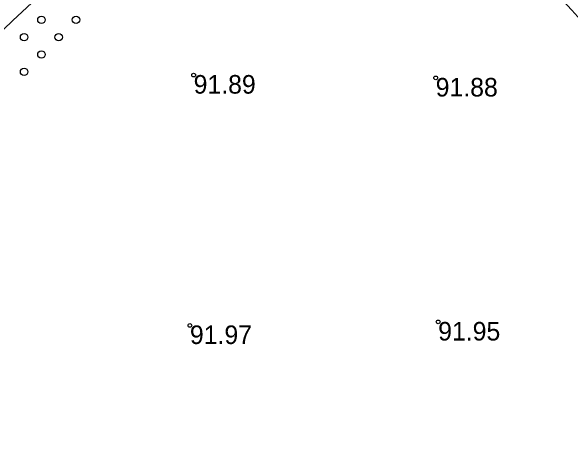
# Model space of a CAD drawing. Extents: x 316000 to 728450, y 314368 to 726000.
# Drawn here: x 726103.9 to 726217, y 315036.8 to 315127.7 of the extents above; entities that cross this region are included whole.
import ezdxf

# ---------------------------------------------------------------- set-up
doc = ezdxf.new("R2010")
doc.units = 0
for name, color, linetype in [('RELJ_AATZ_####_TKST_#', 7, 'Continuous'), ('RELJ_ELEM_####_####_#', 7, 'Continuous'), ('RELJ_HORZ_PAMT_####_#', 7, 'Continuous'), ('RELJ_NOGA_####_####_#', 7, 'Continuous'), ('TERT_ELEM_####_####_#', 7, 'Continuous'), ('TERT_KONT_####_####_#', 7, 'Continuous')]:
    doc.layers.add(name, color=color, linetype=linetype)

msp = doc.modelspace()

# ---------------------------------------------------------------- linework, layer by layer
at = {"layer": 'RELJ_ELEM_####_####_#'}
for centre in [(726140.77, 315114.84), (726189.69, 315114.26), (726190.19, 315064.99), (726140.02, 315064.28)]:
    msp.add_circle(centre, 0.375, dxfattribs=at)
at = {"layer": 'RELJ_HORZ_PAMT_####_#'}
msp.add_spline([(726166.01, 314654.12), (726198.69, 314716.78), (726207.79, 314742.43), (726213.69, 314769.66), (726221.77, 314795.63), (726228.31, 314807.26), (726232.5, 314812.58), (726234.86, 314815.1), (726237.42, 314817.51), (726261.34, 314833.96), (726287.37, 314845.57), (726314.05, 314855.57), (726327.19, 314860.98), (726339.94, 314867.19), (726354.85, 314874.87), (726370.01, 314882.21), (726400.42, 314896.82), (726429.83, 314913.01), (726443.74, 314922.3), (726456.88, 314932.73), (726478.18, 314952.05), (726498.87, 314971.88), (726519.32, 314991.9), (726539.92, 315011.75), (726586.04, 315054.6), (726590.47, 315064.89)], degree=3, dxfattribs=at)
at = {"layer": 'RELJ_NOGA_####_####_#'}
for points in [[(726259.12, 315084.51), (726262.72, 315089.26), (726261.56, 315090.84), (726260.2, 315092.42), (726257.29, 315095.53), (726218.91, 315136.38), (726180.31, 315176.84), (726128.67, 315229.97), (726063.7, 315298.11), (725999.9, 315366.09), (725937.21, 315432.09), (725876.35, 315495.23), (725810.58, 315563.08), (725744.7, 315632.91)], [(725740.86, 315626.98), (725805.54, 315558.12), (725870.39, 315491.15), (725932.8, 315426.8), (725994.98, 315360.84), (726059.66, 315292.12), (726075.75, 315275.46), (726092.08, 315259.04), (726108.47, 315242.67), (726124.69, 315226.14), (726193.27, 315154.03), (726250.06, 315092.6), (726256.32, 315085.83), (726258.82, 315084.29), (726259.12, 315084.51)]]:
    msp.add_spline(points, degree=3, dxfattribs=at)
at = {"layer": 'TERT_ELEM_####_####_#'}
for centre in [(726110, 315126), (726117, 315126), (726106.5, 315122.5), (726113.5, 315122.5), (726110, 315119), (726106.5, 315115.5)]:
    msp.add_circle(centre, 0.75, dxfattribs=at)
at = {"layer": 'TERT_KONT_####_####_#'}
msp.add_spline([(726171.05, 315177.78), (726060.22, 315058.34), (726046.85, 314926.57), (725966, 314840.49), (725918.95, 314808.85), (725841.04, 314808.85), (725695.46, 314898.17)], degree=3, dxfattribs=at)

# ---------------------------------------------------------------- texts
at = {"layer": 'RELJ_AATZ_####_TKST_#'}
for s, p in [('91.89', (726140.77, 315111.09)), ('91.88', (726189.69, 315110.51)), ('91.95', (726190.19, 315061.24)), ('91.97', (726140.02, 315060.53))]:
    msp.add_text(s, height=3.75, dxfattribs=at).set_placement(p)

doc.saveas('drawing.dxf')
